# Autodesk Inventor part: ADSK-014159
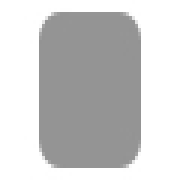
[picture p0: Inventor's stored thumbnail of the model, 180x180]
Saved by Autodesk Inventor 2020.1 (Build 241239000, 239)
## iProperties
Created: 2019-01
Part Number: ADSK-014159
Material: Stahl, weich
Document SubType Name: Modeling
Designer: lutzd
Language: de-DE
Size Designation: 5 x 39,384472 x 39,384472
Categories: <MemberInstance><Categories><Category DisplayName="Sonstige Bauteile" InternalName="5aa15e00-363f-49f2-933f-16f664388e3f" Mnemonic="OTHER"><Category DisplayName
Mass: 60.0398 g
Surface Area: 38.0412 cm^2
Volume: 7.64838 cm^3
Density: 7.85 g/cm^3
Appearance: Halbpoliert
IsCustomPart: 1
Title: end cap
Author: lutzd
Revision Number: -
Dimensions: 39,4x39,4x5 mm
Mass: 0,06 kg
DocNumber: ADSK-014159
Folder: 01 - Themengebiete\Simplification\01 - Packaging machine\
VDS_Category: 3D Komponenten
VDS_NumSchm: Autodesk
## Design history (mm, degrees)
sketch "Sketch1"
  geometry: L1 (0, 20.175)-(0, -21.446); L2 (-20.203, 0)-(20.169, 0); L3 (-19.692, 19.692)-(19.692, 19.692); L4 (19.692, 19.692)-(19.692, -19.692); L5 (19.692, -19.692)-(-19.692, -19.692); L6 (-19.692, -19.692)-(-19.692, 19.692); 1 further point
  constraints: 12 end point, 2 horizontal, 2 parallel, 2 point on line, 1 perpendicular, 1 vertical
  dimensions: "d0" = 39.38447 distance between parallel lines of L5 L3 (= height); "d1" = 19.69224 distance between parallel lines of L2 L3 (= 0.5 x height); "d2" = 39.38447 distance between parallel lines of L6 L4 (= width); "d3" = 19.69224 distance between parallel lines of L6 L1 (= 0.5 x width)
extrude "Extrusion1" new body sketch "Sketch1" distance "d4" = 5 (= thickness); taper "d5" = 0 deg
fillet "Fillet1" dims "d6" = 5 (= fillet), "d7" = 0, "fillet" = 5 [user parameter; used in 1 equation term]
chamfer "Chamfer1" distance "d8" = 0 (computed from chamfer); stored, may be unused: second distance "d9" = 2, angle "d10" = 45 deg; dims "d11" = 0, "chamfer" = 0 [user parameter; used in 1 equation term]
body "Solid1"
other parameters: "thickness" = 5 [user parameter; used in 1 equation term], "width" = 39.38447 [user parameter; used in 2 equation terms], "height" = 39.38447 [user parameter; used in 2 equation terms]
